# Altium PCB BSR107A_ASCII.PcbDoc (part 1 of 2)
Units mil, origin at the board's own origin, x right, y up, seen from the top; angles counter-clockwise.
Board outline 2500 x 2500 mil, 4 copper layers (Top Layer, Signal Layer 1, Signal Layer 2, Bottom Layer), stack 64.4 mil thick; 58 components, 15 nets, 89 pads, 265 vias.
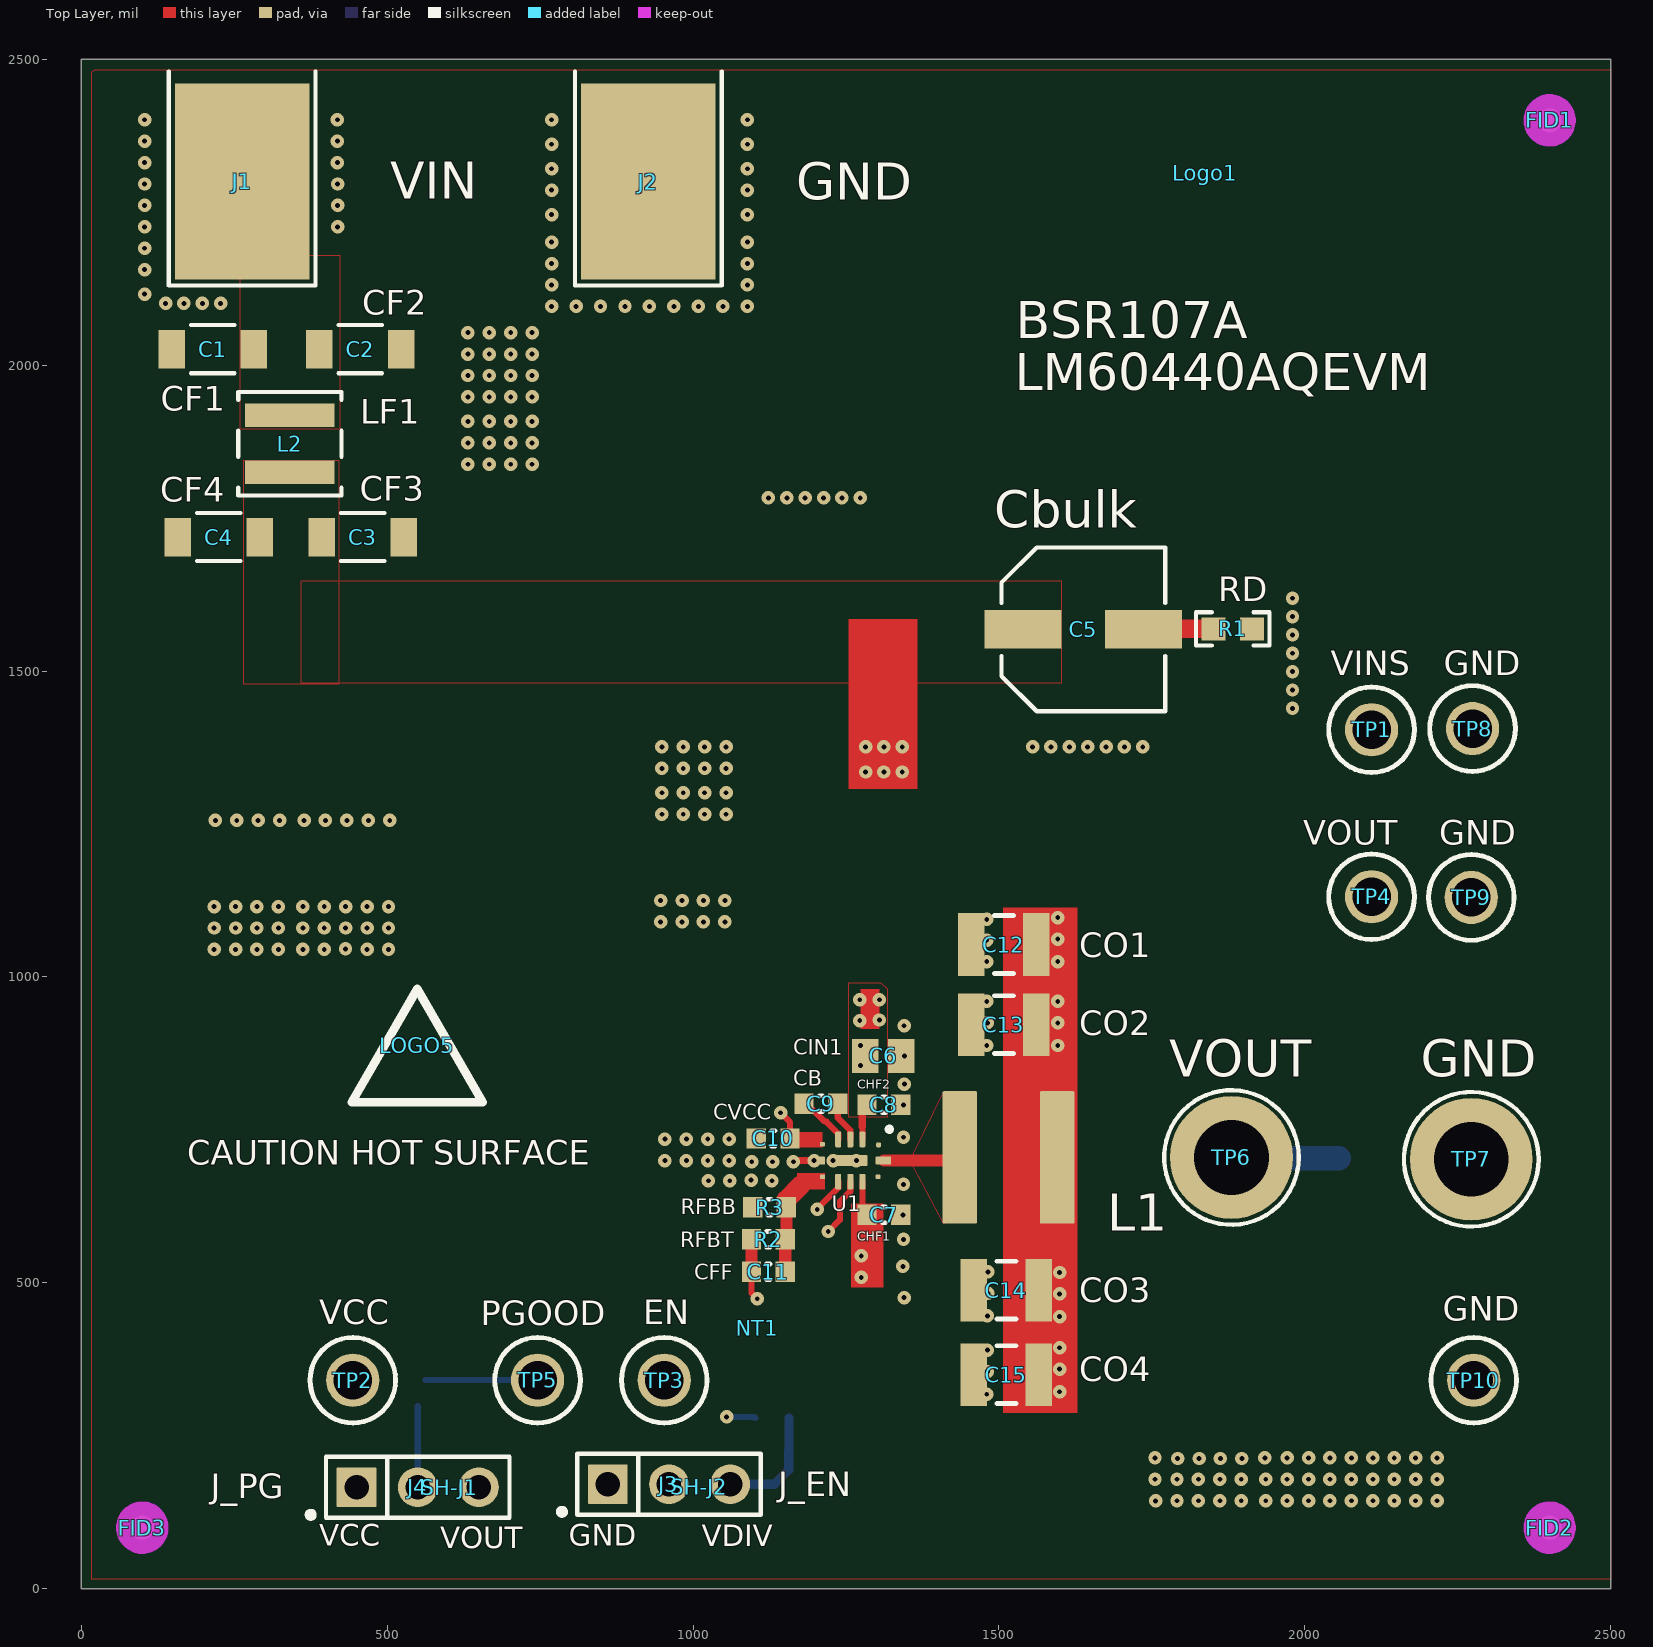
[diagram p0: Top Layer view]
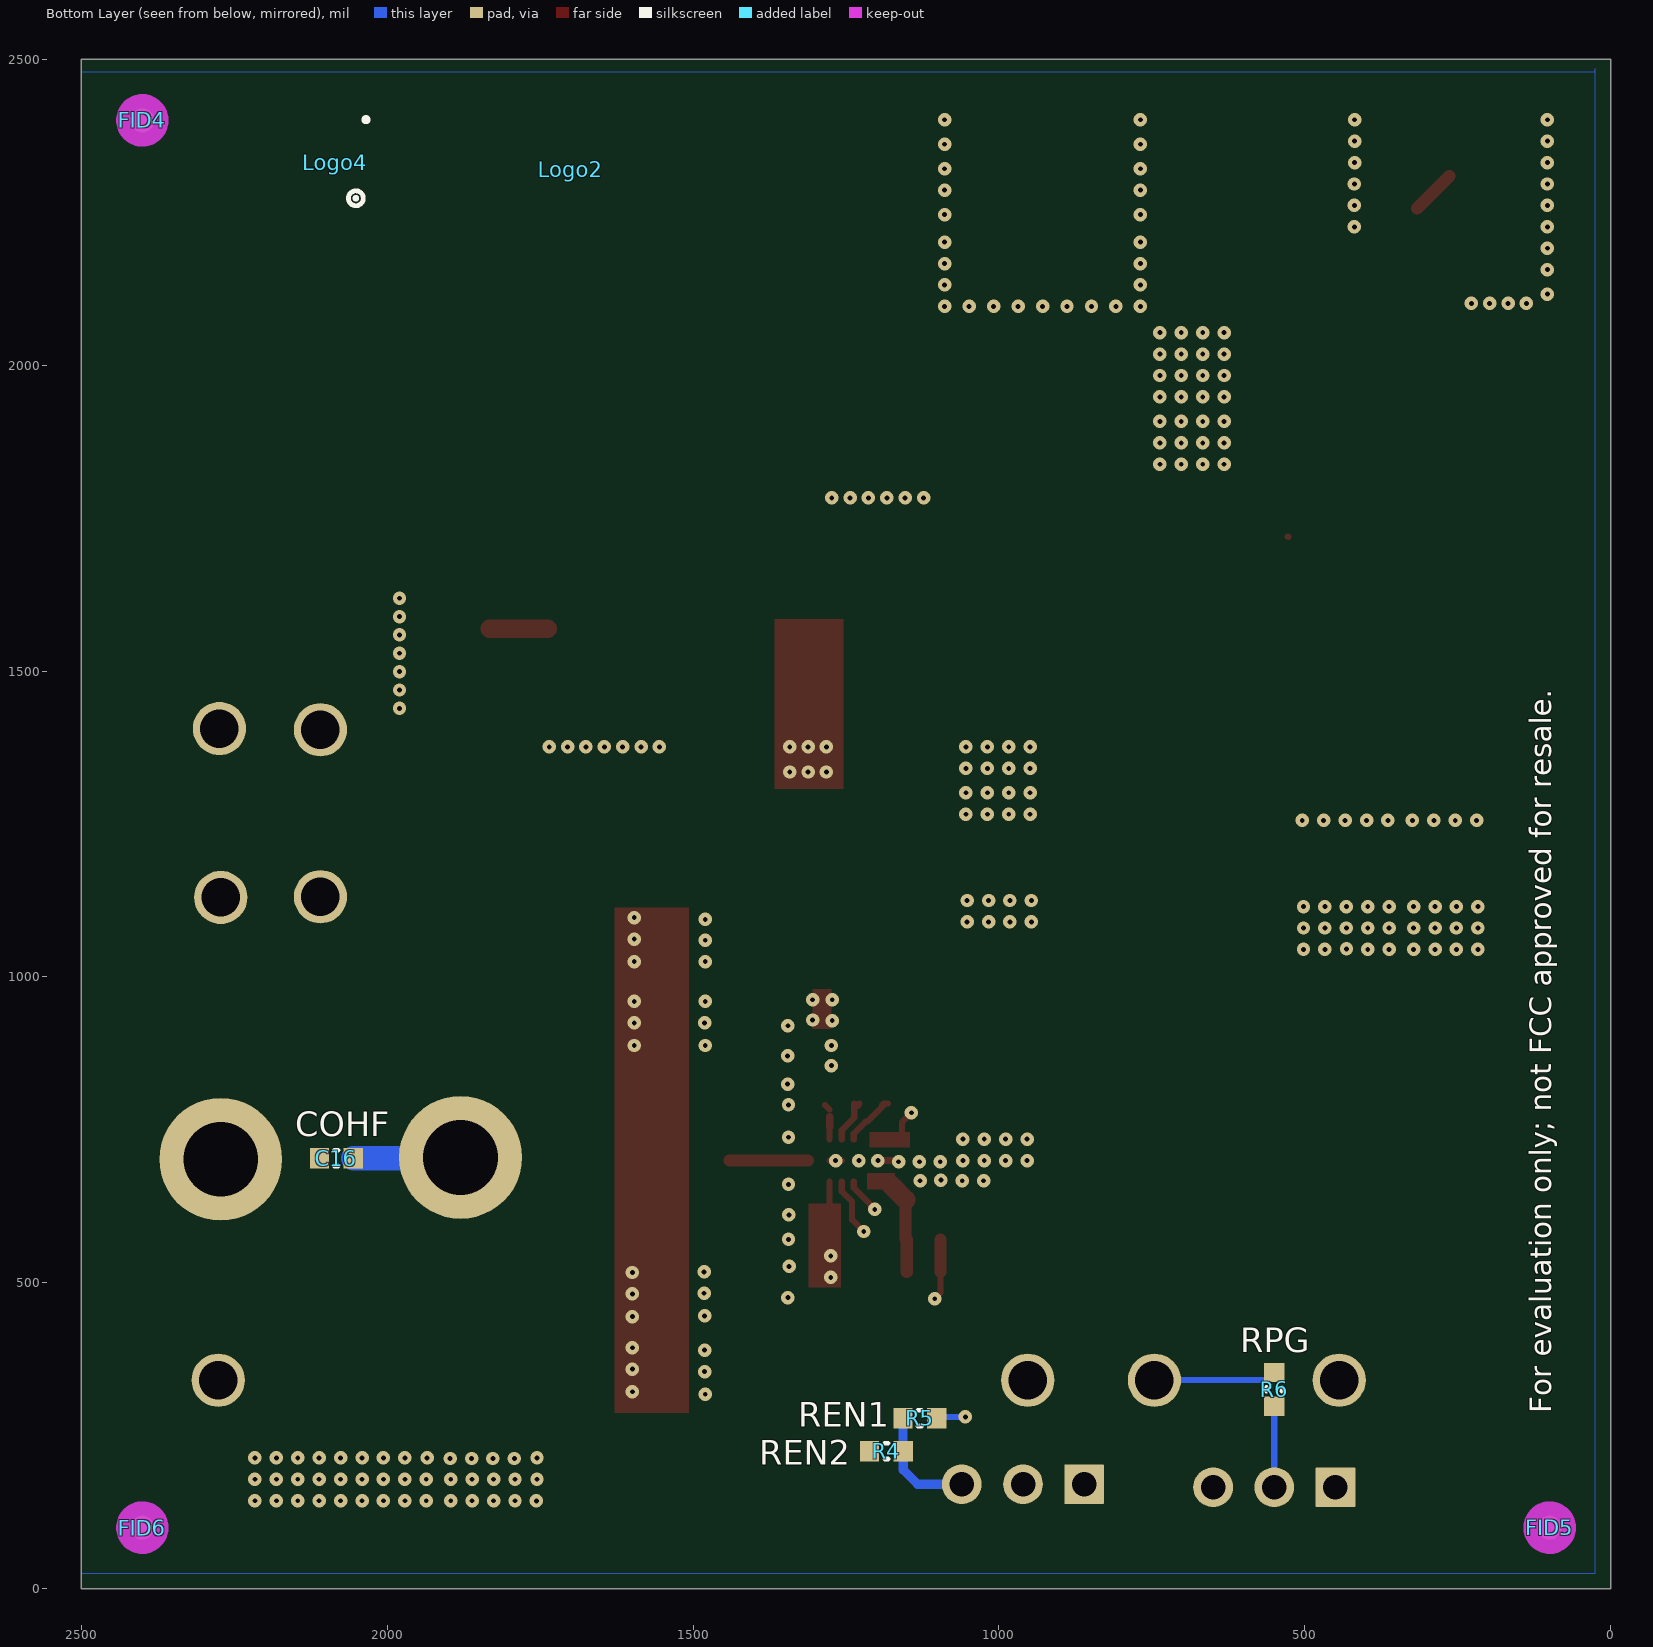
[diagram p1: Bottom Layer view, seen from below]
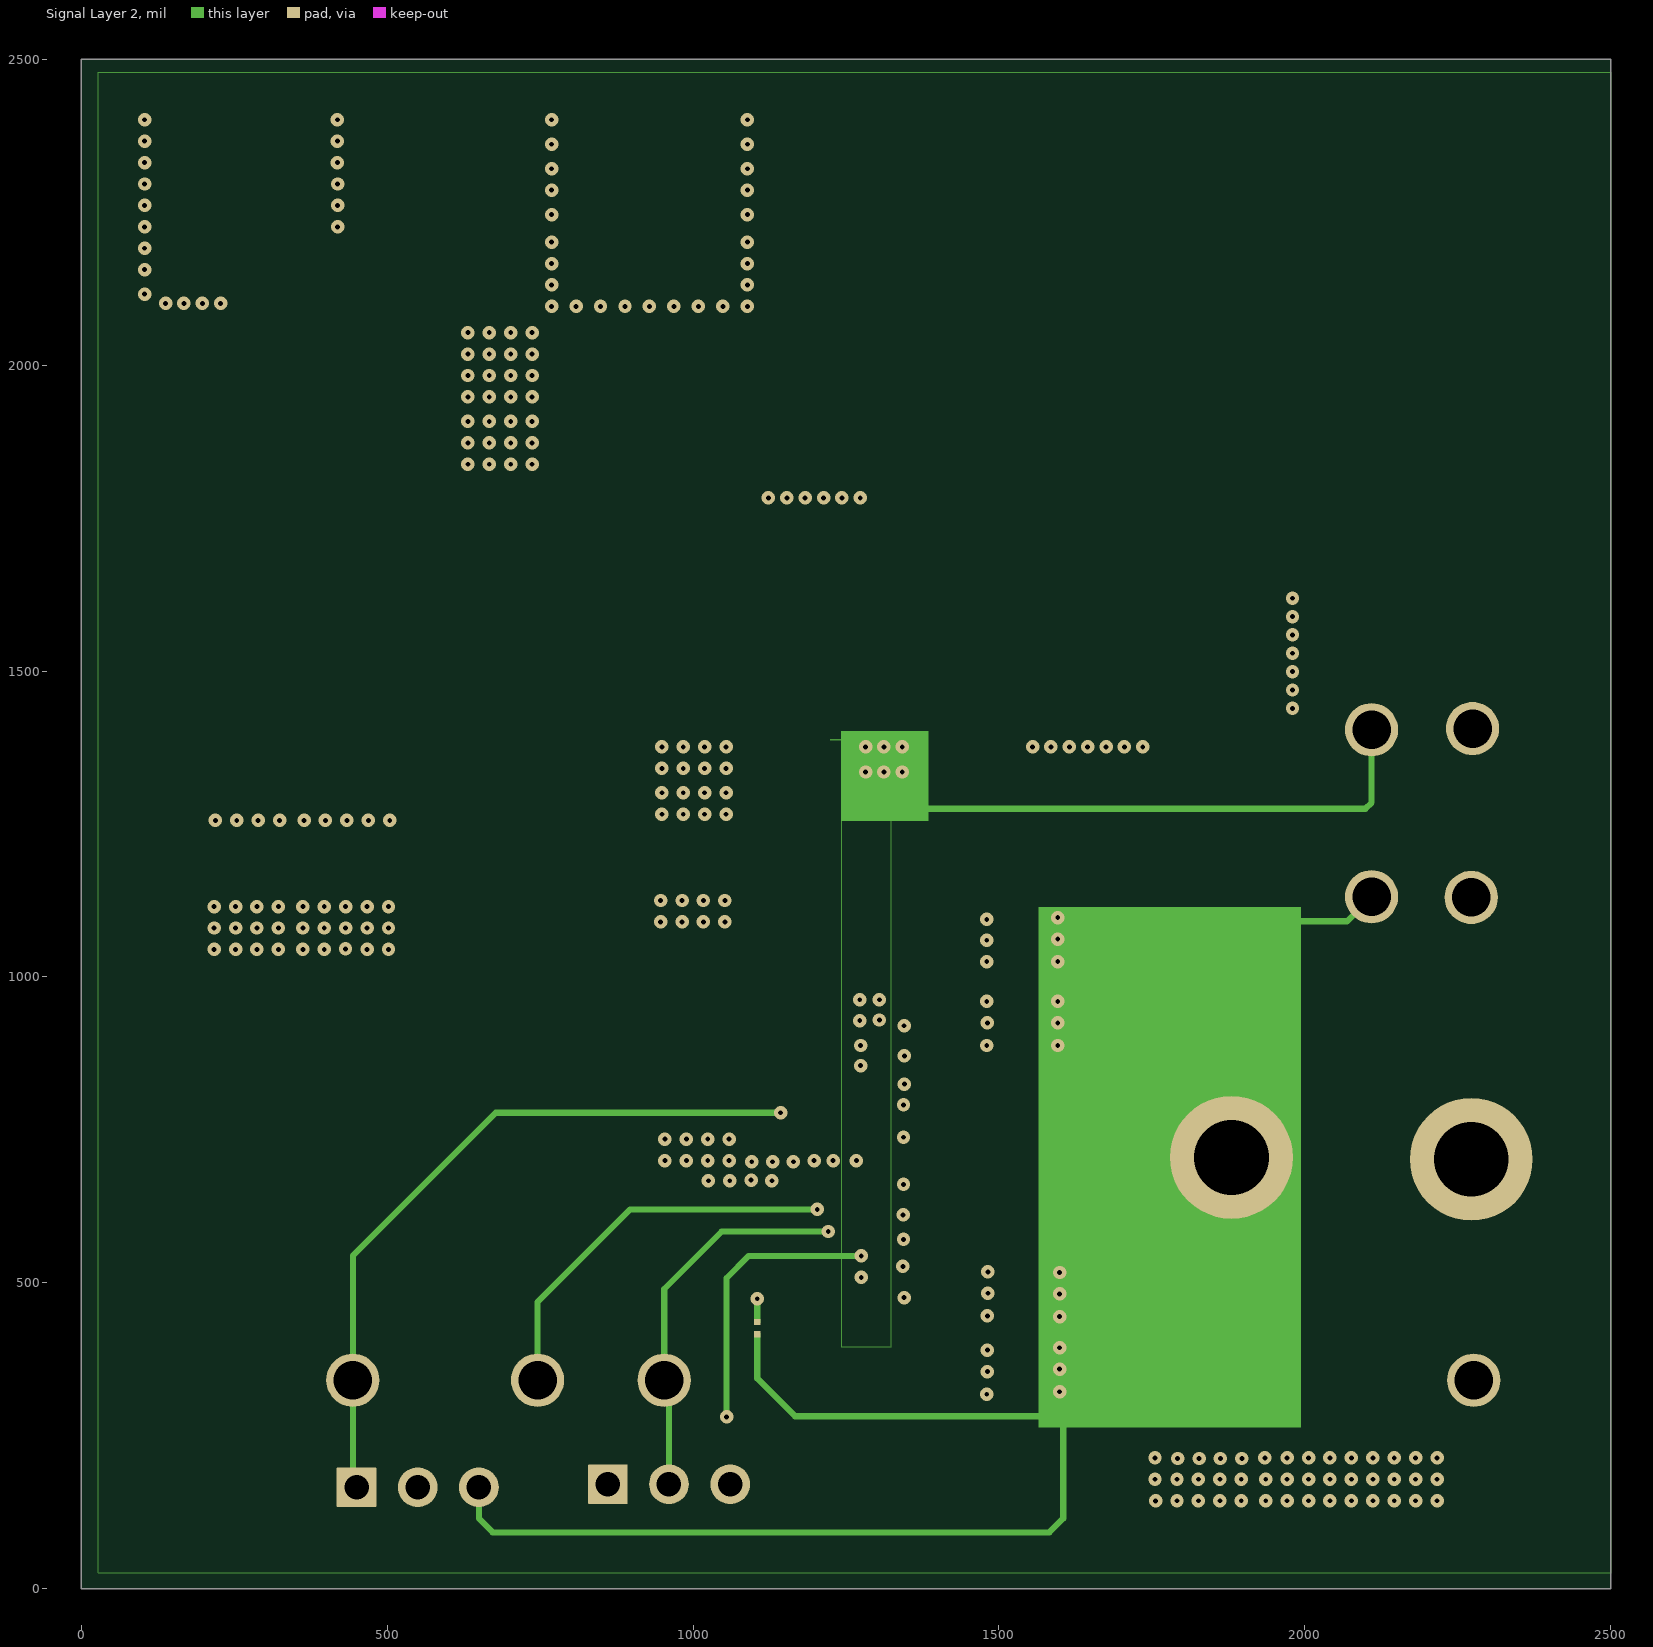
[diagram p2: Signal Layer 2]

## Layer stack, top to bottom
Top Solder: solder mask 0.4, Solder Resist, Dk 3.5
Top Layer: signal copper 2.8
Dielectric 3: core 14, FR-4 High TG, Dk 4.2
Signal Layer 1: signal copper 1.4
Dielectric 2: core 28, FR-4 High TG, Dk 4.2
Signal Layer 2: signal copper 1.4
Dielectric1: core 14, FR-4 HIgh TG, Dk 4.2
Bottom Layer: signal copper 2.8
Bottom Solder: solder mask 0.4, Solder Resist, Dk 3.5

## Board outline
0,0 0,2500 2500,2500 2500,0

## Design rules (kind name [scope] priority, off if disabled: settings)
AcuteAngle [All] p0: scope1count=1 scope1_0_kind=Board scope1_0_value=Board scope2count=1 scope2_0_kind=Board scope2_0_value=Board commentlength=0 minimum=4.50000000000000E+0001
AcuteAngle [All] p1: minimum=4.50000000000000E+0001 checktracksonly=FALSE
AssemblyTestPointUsage [All] p0: scope1count=1 scope1_0_kind=Board scope1_0_value=Board scope2count=1 scope2_0_kind=Board scope2_0_value=Board commentlength=0
AssemblyTestPointUsage [All] p1: valid=2
AssemblyTestpoint [All] p0: scope1count=1 scope1_0_kind=Board scope1_0_value=Board scope2count=1 scope2_0_kind=Board scope2_0_value=Board commentlength=0
BoardOutlineClearance [All] p0 off: scope1count=1 scope1_0_kind=Board scope1_0_value=Board scope2count=1 scope2_0_kind=Board scope2_0_value=Board commentlength=172 gap=40 // Protel DXP Scope 1 Expression Was: OnCopper and Not InComponentClass('Logo') and not InComponentClass('FiducialMark') and not InRegion(1000,500,4000,800) and not InPoly
BoardOutlineClearance BoardOutlineClearance_Poly [All] p0 off: scope1count=1 scope1_0_kind=Board scope1_0_value=Board scope2count=1 scope2_0_kind=Board scope2_0_value=Board commentlength=58 gap=25 // Protel DXP Scope 1 Expression Was: OnCopper and IsPoly
BoardOutlineClearance BoardOutlineClearance_MountingHoles [All] p0 off: scope1count=1 scope1_0_kind=Board scope1_0_value=Board scope2count=1 scope2_0_kind=Board scope2_0_value=Board commentlength=86 gap=40 // Protel DXP Scope 1 Expression Was: OnCopper and InComponentClass('Mounting Holes')
BoardOutlineClearance BoardOutlineClearance_MountingHoles [OnCopper and InComponentClass('Mounting Holes')] p1: gap=40 ignorepadtopadclearanceinfootprint=FALSE
BoardOutlineClearance BoardOutlineClearance_Poly [OnCopper and IsPoly] p2: gap=25 ignorepadtopadclearanceinfootprint=FALSE
BoardOutlineClearance [OnCopper and Not InComponentClass('Logo') and not InComponentClass('FiducialMark') and not InRegion(1000,500,4000,800) and not InPoly] p3: gap=40 ignorepadtopadclearanceinfootprint=FALSE
Clearance [All] p0: scope1count=1 scope1_0_kind=Board scope1_0_value=Board scope2count=1 scope2_0_kind=Board scope2_0_value=Board commentlength=0 gap=7.79
Clearance Clearance_FiducialMark [All] p0 off: scope1count=1 scope1_0_kind=Board scope1_0_value=Board scope2count=1 scope2_0_kind=Board scope2_0_value=Board commentlength=81 gap=0 // Protel DXP Scope 2 Expression Was: IsPad and InComponentClass('FiducialMark')
Clearance Clearance_Poly [All] p0 off: scope1count=1 scope1_0_kind=Board scope1_0_value=Board scope2count=1 scope2_0_kind=Board scope2_0_value=Board commentlength=48 gap=10 // Protel DXP Scope 1 Expression Was: InPolygon
Clearance Clearance_Keepouts [All] p0 off: scope1count=1 scope1_0_kind=Board scope1_0_value=Board scope2count=1 scope2_0_kind=Board scope2_0_value=Board commentlength=99 gap=0 // Protel DXP Scope 2 Expression Was: ((IsTrack Or IsArc) And Not InPoly) And IsFree and IsKeepOut
Clearance Clearance_Keepouts [((IsTrack Or IsArc) And Not InPoly) And IsFree and IsKeepOut vs ((IsTrack Or IsArc) And Not InPoly) And IsFree and IsKeepOut] p1: gap=0 ignorepadtopadclearanceinfootprint=FALSE
Clearance Clearance_Poly [InPolygon] p2: gap=10 ignorepadtopadclearanceinfootprint=FALSE except(0: Arc-Hole Track-Hole SMDPad-Hole THPad-Hole Via-Hole Fill-Hole Poly-Hole Region-Hole Text-Hole)
Clearance Clearance_FiducialMark [IsKeepOut and InComponentClass('FiducialMark') vs IsPad and InComponentClass('FiducialMark')] p3: gap=0 ignorepadtopadclearanceinfootprint=FALSE
Clearance [All] p4: gap=7.79 ignorepadtopadclearanceinfootprint=FALSE
ComponentClearance [All] p0: scope1count=1 scope1_0_kind=Board scope1_0_value=Board scope2count=1 scope2_0_kind=Board scope2_0_value=Board commentlength=0 gap=30 collisioncheckmode=3
ComponentClearance ComponentClearance_THtoTH [All] p0 off: scope1count=1 scope1_0_kind=Board scope1_0_value=Board scope2count=1 scope2_0_kind=Board scope2_0_value=Board commentlength=54 gap=30 collisioncheckmode=3 // Protel DXP Scope 2 Expression Was: IsThruComponent
ComponentClearance ComponentClearance_THtoSMT [All] p0 off: scope1count=1 scope1_0_kind=Board scope1_0_value=Board scope2count=1 scope2_0_kind=Board scope2_0_value=Board commentlength=53 gap=40 collisioncheckmode=3 // Protel DXP Scope 2 Expression Was: IsSMTComponent
ComponentClearance ComponentClearance_SmallPassives [All] p0 off: scope1count=1 scope1_0_kind=Board scope1_0_value=Board scope2count=1 scope2_0_kind=Board scope2_0_value=Board commentlength=508 gap=14.96 collisioncheckmode=3 // Protel DXP Scope 2 Expression Was: HasFootprint('0201*') or HasFootprint('0402*') or HasFootprint('0508') or HasFootprint('0603*') or HasFootprint('0612') or HasFootprint('0805*') or HasFootprint('0815*') or HasFootprint('0830*') or HasFootprint('1206*') or HasFootprint('1210*') or HasFootprint('1808*') or HasFootprint('1812*') or HasFootprint('1825*') or HasFootprint('2010*') or HasFootprint('2220*') or HasFootprint('2225*') or HasFootprint('2512*') or HasFootprint('2728*') or HasFootprint('3518*')
ComponentClearance ComponentClearance_MountingHoles [All] p0: scope1count=1 scope1_0_kind=ComponentClass scope1_0_value="Mounting Holes" scope2count=1 scope2_0_kind=Board scope2_0_value=Board commentlength=0 gap=250 collisioncheckmode=3
ComponentClearance ComponentClearance_ScrewToNut [All] p0 off: scope1count=1 scope1_0_kind=Board scope1_0_value=Board scope2count=1 scope2_0_kind=Board scope2_0_value=Board commentlength=71 gap=5 collisioncheckmode=3 // Protel DXP Scope 2 Expression Was: (HasFootprint('Keystone_1902C'))
ComponentClearance ComponentClearance_Logo [All] p0: scope1count=1 scope1_0_kind=ComponentClass scope1_0_value=Logo scope2count=1 scope2_0_kind=Board scope2_0_value=Board commentlength=0 gap=50 collisioncheckmode=3
ComponentClearance ComponentClearance_Shunt [All] p0: scope1count=1 scope1_0_kind=ComponentClass scope1_0_value=Header scope2count=1 scope2_0_kind=ComponentClass scope2_0_value=Shunt commentlength=0 gap=0 collisioncheckmode=3
ComponentClearance ComponentClearance_MountingHoles_FiducialMarks [All] p0: scope1count=1 scope1_0_kind=ComponentClass scope1_0_value="Mounting Holes" scope2count=1 scope2_0_kind=ComponentClass scope2_0_value=FiducialMark commentlength=0 gap=50 collisioncheckmode=3
ComponentClearance ComponentClearance_MountingHoles_FiducialMarks [InComponentClass('Mounting Holes') vs InComponentClass('FiducialMark')] p1: gap=50 collisioncheckmode=3 verticalgap=10 showdistances=FALSE
ComponentClearance ComponentClearance_Shunt [InComponentClass('Header') vs InComponentClass('Shunt')] p2: gap=0 collisioncheckmode=3 verticalgap=0 showdistances=FALSE
ComponentClearance ComponentClearance_Logo [InComponentClass('Logo')] p3: gap=50 collisioncheckmode=3 verticalgap=10 showdistances=FALSE
ComponentClearance ComponentClearance_ScrewToNut [(HasFootprint('NY PMS 440 0025 PH')) vs (HasFootprint('Keystone_1902C'))] p4: gap=5 collisioncheckmode=3 verticalgap=10 showdistances=FALSE
ComponentClearance ComponentClearance_MountingHoles [InComponentClass('Mounting Holes')] p5: gap=250 collisioncheckmode=3 verticalgap=100000 showdistances=FALSE
ComponentClearance ComponentClearance_SmallPassives [HasFootprint('0201*') or HasFootprint('0402*') or HasFootprint('0508') or HasFootprint('0603*') or HasFootprint('0612') or HasFootprint('0805*') or HasFootprint('0815*') or HasFootprint('0830*') or HasFootprint('1206*') or HasFootprint('1210*') or HasFootprint('1808*') or HasFootprint('1812*') or HasFootprint('1825*') or HasFootprint('2010*') or HasFootprint('2220*') or HasFootprint('2225*') or HasFootprint('2512*') or HasFootprint('2728*') or HasFootprint('3518*') vs HasFootprint('0201*') or HasFootprint('0402*') or HasFootprint('0508') or HasFootprint('0603*') or HasFootprint('0612') or HasFootprint('0805*') or HasFootprint('0815*') or HasFootprint('0830*') or HasFootprint('1206*') or HasFootprint('1210*') or HasFootprint('1808*') or HasFootprint('1812*') or HasFootprint('1825*') or HasFootprint('2010*') or HasFootprint('2220*') or HasFootprint('2225*') or HasFootprint('2512*') or HasFootprint('2728*') or HasFootprint('3518*')] p6: gap=14.96 collisioncheckmode=3 verticalgap=10 showdistances=FALSE
ComponentClearance ComponentClearance_THtoSMT [IsThruComponent vs IsSMTComponent] p7: gap=40 collisioncheckmode=3 verticalgap=30 showdistances=FALSE
ComponentClearance ComponentClearance_THtoTH [IsThruComponent vs IsThruComponent] p8: gap=30 collisioncheckmode=3 verticalgap=30 showdistances=FALSE
ComponentClearance [All] p9: gap=30 collisioncheckmode=3 verticalgap=10 showdistances=FALSE
DiffPairsRouting [All] p0: scope1count=1 scope1_0_kind=Board scope1_0_value=Board scope2count=1 scope2_0_kind=Board scope2_0_value=Board commentlength=0
DiffPairsRouting [All] p1: maxlimit=100 minlimit=10 mostfreqgap=10 toplayer_minwidth=15 toplayer_maxwidth=15 toplayer_prefwidth=15 midlayer1_minwidth=15 midlayer1_maxwidth=15 midlayer1_prefwidth=15 midlayer2_minwidth=15 midlayer2_maxwidth=15 midlayer2_prefwidth=15 bottomlayer_minwidth=15 bottomlayer_maxwidth=15 bottomlayer_prefwidth=15 maxuncoupledlength=1000
FabricationTestPointUsage TestPointUsage [All] p0: scope1count=1 scope1_0_kind=Board scope1_0_value=Board scope2count=1 scope2_0_kind=Board scope2_0_value=Board commentlength=0 valid=2 allowmultiple=FALSE
FabricationTestPointUsage TestPointUsage [All] p1: valid=2 allowmultiple=FALSE
FabricationTestpoint Testpoint [All] p0: scope1count=1 scope1_0_kind=Board scope1_0_value=Board scope2count=1 scope2_0_kind=Board scope2_0_value=Board commentlength=0 side=3 testpointundercomponent=TRUE minsize=40 maxsize=100 preferedsize=60 minholesize=0 maxholesize=40 preferedholesize=32 testpointgrid=1
FabricationTestpoint Testpoint [All] p1: side=3 testpointundercomponent=TRUE minsize=40 maxsize=100 preferedsize=60 minholesize=0 maxholesize=40 preferedholesize=32 testpointgrid=1 allowsidetop=TRUE allowsidebottom=TRUE usegrid=TRUE gridtolerance=0.01
FanoutControl Fanout_Small [All] p0 off: scope1count=1 scope1_0_kind=Board scope1_0_value=Board scope2count=1 scope2_0_kind=Board scope2_0_value=Board commentlength=84 // Protel DXP Scope 1 Expression Was: (CompPinCount < 5)   Fanout_Small (Default Rule)
FanoutControl Fanout_Default [All] p0: scope1count=1 scope1_0_kind=Board scope1_0_value=Board scope2count=1 scope2_0_kind=Board scope2_0_value=Board commentlength=30 // Fanout_Default (Default Rule)
FanoutControl Fanout_SOIC [All] p0 off: scope1count=1 scope1_0_kind=Board scope1_0_value=Board scope2count=1 scope2_0_kind=Board scope2_0_value=Board commentlength=71 // Protel DXP Scope 1 Expression Was: IsSOIC   Fanout_SOIC (Default Rule)
FanoutControl Fanout_BGA [All] p0 off: scope1count=1 scope1_0_kind=Board scope1_0_value=Board scope2count=1 scope2_0_kind=Board scope2_0_value=Board commentlength=69 // Protel DXP Scope 1 Expression Was: IsBGA   Fanout_BGA (Default Rule)
FanoutControl Fanout_LCC [All] p0 off: scope1count=1 scope1_0_kind=Board scope1_0_value=Board scope2count=1 scope2_0_kind=Board scope2_0_value=Board commentlength=69 // Protel DXP Scope 1 Expression Was: IsLCC   Fanout_LCC (Default Rule)
FanoutControl Fanout_LCC [IsLCC] p1: bgadir=Out bgaviamode=Centered fanoutstyle=Auto fanoutdirection=Alternating viagrid=1 // Fanout_LCC (Default Rule)
FanoutControl Fanout_BGA [IsBGA] p2: bgadir=Out bgaviamode=Centered fanoutstyle=Auto fanoutdirection=Alternating viagrid=1 // Fanout_BGA (Default Rule)
FanoutControl Fanout_Default [All] p4: bgadir=Out bgaviamode=Centered fanoutstyle=Auto fanoutdirection=Alternating viagrid=1 // Fanout_Default (Default Rule)
FanoutControl Fanout_Small [(CompPinCount < 5)] p5: bgadir=Out bgaviamode=Centered fanoutstyle=Auto fanoutdirection=OutThenIn viagrid=1 // Fanout_Small (Default Rule)
Height [All] p0: scope1count=1 scope1_0_kind=Board scope1_0_value=Board scope2count=1 scope2_0_kind=Board scope2_0_value=Board commentlength=0
HoleSize [All] p0: scope1count=1 scope1_0_kind=Board scope1_0_value=Board scope2count=1 scope2_0_kind=Board scope2_0_value=Board commentlength=0 absolutevalues=TRUE maxlimit=251 minlimit=7.87 maxpercent=80.000 minpercent=20.000
HoleSize [All] p1: absolutevalues=TRUE maxlimit=251 minlimit=7.87 maxpercent=80.000 minpercent=20.000
HoleToHoleClearance [All] p0: scope1count=1 scope1_0_kind=Board scope1_0_value=Board scope2count=1 scope2_0_kind=Board scope2_0_value=Board commentlength=0
LayerPairs [All] p0: scope1count=1 scope1_0_kind=Board scope1_0_value=Board scope2count=1 scope2_0_kind=Board scope2_0_value=Board commentlength=0 enforce=TRUE
MinimumAnnularRing [All] p0: scope1count=1 scope1_0_kind=Board scope1_0_value=Board scope2count=1 scope2_0_kind=Board scope2_0_value=Board commentlength=0 minimumring=5
MinimumAnnularRing MinimumAnnularRing_ThermalPadVias [All] p0 off: scope1count=1 scope1_0_kind=Board scope1_0_value=Board scope2count=1 scope2_0_kind=Board scope2_0_value=Board commentlength=63 minimumring=5.91 // Protel DXP Scope 1 Expression Was: IsVia and InAnyComponent
MinimumAnnularRing MinimumAnnularRing_ThermalPadVias [IsVia and InAnyComponent] p1: minimumring=5.91
MinimumAnnularRing [All] p2: minimumring=5
MinimumSolderMaskSliver [All] p0: scope1count=1 scope1_0_kind=Board scope1_0_value=Board scope2count=1 scope2_0_kind=Board scope2_0_value=Board commentlength=0
MinimumSolderMaskSliver MinimumSolderMaskSliver_Logo [All] p0: scope1count=1 scope1_0_kind=ComponentClass scope1_0_value=Logo scope2count=1 scope2_0_kind=ComponentClass scope2_0_value=Logo commentlength=0
MinimumSolderMaskSliver MinimumSolderMaskSliver_Logo [InComponentClass('Logo') vs InComponentClass('Logo')] p1: minsoldermaskwidth=0.7
MinimumSolderMaskSliver [All] p2: minsoldermaskwidth=3.94
NetAntennae [All] p0: scope1count=1 scope1_0_kind=Board scope1_0_value=Board scope2count=1 scope2_0_kind=Board scope2_0_value=Board commentlength=0
PasteMaskExpansion [All] p0: scope1count=1 scope1_0_kind=Board scope1_0_value=Board scope2count=1 scope2_0_kind=Board scope2_0_value=Board commentlength=0 expansion=0
PlaneClearance [All] p0: scope1count=1 scope1_0_kind=Board scope1_0_value=Board scope2count=1 scope2_0_kind=Board scope2_0_value=Board commentlength=0 clearance=20
PlaneConnect [All] p0: scope1count=1 scope1_0_kind=Board scope1_0_value=Board scope2count=1 scope2_0_kind=Board scope2_0_value=Board commentlength=0 planeconnectstyle=Relief reliefexpansion=10 reliefentries=4 reliefconductorwidth=10 reliefairgap=10
PlaneConnect [All] p1: planeconnectstyle=Relief reliefexpansion=10 reliefentries=4 reliefconductorwidth=10 reliefairgap=10
PolygonConnect [All] p0: scope1count=1 scope1_0_kind=Board scope1_0_value=Board scope2count=1 scope2_0_kind=Board scope2_0_value=Board commentlength=0 connectstyle=Direct reliefconductorwidth=10 reliefentries=4 polygonreliefangle="90 Angle"
PolygonConnect [All] p1: connectstyle=Direct reliefconductorwidth=10 reliefentries=4 polygonreliefangle="90 Angle" airgapwidth=10
RoutingCorners [All] p0: scope1count=1 scope1_0_kind=Board scope1_0_value=Board scope2count=1 scope2_0_kind=Board scope2_0_value=Board commentlength=0 cornerstyle=45-Degree minsetback=100 maxsetback=100
RoutingLayers [All] p0: scope1count=1 scope1_0_kind=Board scope1_0_value=Board scope2count=1 scope2_0_kind=Board scope2_0_value=Board commentlength=0 top layer=Automatic mid layer 1=Automatic mid layer 2=Automatic bottom layer=Automatic
RoutingPriority [All] p0: scope1count=1 scope1_0_kind=Board scope1_0_value=Board scope2count=1 scope2_0_kind=Board scope2_0_value=Board commentlength=0
RoutingTopology [All] p0: scope1count=1 scope1_0_kind=Board scope1_0_value=Board scope2count=1 scope2_0_kind=Board scope2_0_value=Board commentlength=0 topology=Shortest
RoutingVias [All] p0: scope1count=1 scope1_0_kind=Board scope1_0_value=Board scope2count=1 scope2_0_kind=Board scope2_0_value=Board commentlength=0 holewidth=16 width=34 viastyle="Through Hole" minholewidth=7.87 minwidth=18 maxholewidth=40 maxwidth=65
RoutingVias ThermalPadVias [All] p0 off: scope1count=1 scope1_0_kind=Board scope1_0_value=Board scope2count=1 scope2_0_kind=Board scope2_0_value=Board commentlength=63 holewidth=7.87 width=19.68 viastyle="Through Hole" minholewidth=7.87 minwidth=19.68 maxholewidth=12.99 maxwidth=23.62 // Protel DXP Scope 1 Expression Was: IsVia and InAnyComponent
RoutingVias ThermalPadVias [IsVia and InAnyComponent] p1: holewidth=7.87 width=19.68 viastyle="Through Hole" minholewidth=7.87 minwidth=19.68 maxholewidth=12.99 maxwidth=23.62
RoutingVias [All] p2: holewidth=16 width=34 viastyle="Through Hole" minholewidth=7.87 minwidth=18 maxholewidth=40 maxwidth=65
ShortCircuit [All] p0: scope1count=1 scope1_0_kind=Board scope1_0_value=Board scope2count=1 scope2_0_kind=Board scope2_0_value=Board commentlength=0 allowed=FALSE
SilkToBoardRegionClearance [All] p0 off: scope1count=1 scope1_0_kind=Board scope1_0_value=Board scope2count=1 scope2_0_kind=Board scope2_0_value=Board commentlength=130 // Protel DXP Scope 1 Expression Was: Not ((IsComment or IsDesignator) And (Hide <> 'False')) and not InRegion(1000,500,4000,800)
SilkToBoardRegionClearance [Not ((IsComment or IsDesignator) And (Hide <> 'False')) and not InRegion(1000,500,4000,800)] p1:
SilkToSilkClearance [All] p0: scope1count=1 scope1_0_kind=Board scope1_0_value=Board scope2count=1 scope2_0_kind=Board scope2_0_value=Board commentlength=0
SilkToSilkClearance SilkToSilkClearance_Pb-FreeLogo [All] p0 off: scope1count=1 scope1_0_kind=Board scope1_0_value=Board scope2count=1 scope2_0_kind=Board scope2_0_value=Board commentlength=120 // Protel DXP Scope 2 Expression Was: (HasFootprint('Pb-Free_Overlay_Medium') OR HasFootprint('Pb-Free_Overlay_Small'))
SilkToSilkClearance SilkToSilkClearance_Pb-FreeLogo [(HasFootprint('Pb-Free_Overlay_Medium') OR HasFootprint('Pb-Free_Overlay_Small')) vs (HasFootprint('Pb-Free_Overlay_Medium') OR HasFootprint('Pb-Free_Overlay_Small'))] p1: silktosilkclearance=0
SilkToSilkClearance [All] p2: silktosilkclearance=4
SilkToSolderMaskClearance "Silk to Solder Mask Opening" [All] p0: scope1count=1 scope1_0_kind=Board scope1_0_value=Board scope2count=1 scope2_0_kind=Board scope2_0_value=Board commentlength=0
SilkToSolderMaskClearance SilkToComponentPadClearance [All] p0 off: scope1count=1 scope1_0_kind=Board scope1_0_value=Board scope2count=1 scope2_0_kind=Board scope2_0_value=Board commentlength=87 // Protel DXP Scope 1 Expression Was: (IsPad or IsFill or IsRegion) and InAnycomponent
SilkToSolderMaskClearance SilkToComponentPadClearance [(IsPad or IsFill or IsRegion) and InAnycomponent] p1: minsilkscreentomaskgap=5 clearancetoexposedcopper=TRUE
SilkToSolderMaskClearance "Silk to Solder Mask Opening" [All] p2: minsilkscreentomaskgap=4 clearancetoexposedcopper=FALSE
SolderMaskExpansion [All] p0: scope1count=1 scope1_0_kind=Board scope1_0_value=Board scope2count=1 scope2_0_kind=Board scope2_0_value=Board commentlength=0 expansion=1.97
SolderMaskExpansion [All] p1: expansion=1.97
UnRoutedNet [All] p0: scope1count=1 scope1_0_kind=Board scope1_0_value=Board scope2count=1 scope2_0_kind=Board scope2_0_value=Board commentlength=0
UnpouredPolygon [All] p0: scope1count=1 scope1_0_kind=Board scope1_0_value=Board scope2count=1 scope2_0_kind=Board scope2_0_value=Board commentlength=0
Width [All] p0: scope1count=1 scope1_0_kind=Board scope1_0_value=Board scope2count=1 scope2_0_kind=Board scope2_0_value=Board commentlength=0 maxlimit=100 minlimit=6 preferedwidth=10
Width [All] p1: maxlimit=100 minlimit=6 preferedwidth=10 checkconnectedcopper=TRUE
15 further rules are at their usual default settings.

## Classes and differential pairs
component class FiducialMark: FID1 FID2 FID3 FID4 FID5 FID6
component class Shunt: SH-J1 SH-J2
component class Header: J3 J4
component class BSR107A_EVM: 3 C1 C2 C3 C4 C5 C6 C7 C8 C9 C10 C11 C12 C13 C14 C15 C16 CB CHF2 CIN1 COUT1 GND GND4 GND5 J1 J2 J3 J4 L1 L2 NT1 R1 R2 R3 R4 R5 R6 TP1 TP2 TP3 TP4 TP5 TP6 TP7 TP8 TP9 TP10 U1 vin
component class AssemblyNote: ZZ2 ZZ3 ZZ4 ZZ5 ZZ6
component class BSR107A_EVM_Hardware: FID1 FID2 FID3 FID4 FID5 FID6 Logo1 Logo2 Logo3 Logo4 LOGO5 SH-J1 SH-J2 ZZ2 ZZ3 ZZ4 ZZ5 ZZ6
component class Logo: Logo1

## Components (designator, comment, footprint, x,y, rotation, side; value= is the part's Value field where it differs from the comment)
C1 "CF1" 1206_180 215,2026 r180 top
C2 "CF2" 1206_180 456,2026 r0 top
C3 "CF3" 1206_180 460,1719 r0 top
C4 "CF4" 1206_180 225,1719 r180 top
C5 "Cbulk" SM_RADIAL_D 1638,1568 r0 top
C6 "CIN1" 0805L 1311,871 r0 top
C7 "CHF1" 0603L 1312,611 r0 top
C8 "CHF2" 0603L 1312,791 r0 top
C9 "CB" 0603L 1209,793 r180 top
C10 "CVCC" 0603L 1131,736 r180 top
C11 "CFF" 0603L 1123,518 r0 top
C12 "CO1" 1210L 1508,1053 r180 top
C13 "CO2" 1210_270L 1508,922 r180 top
C14 "CO3" 1210_270L 1512,488 r180 top
C15 "CO4" 1210L 1512,350 r180 top
C16 "COHF" 0603L 2083,704 r0 bottom
FID1 "Fiducial" Fiducial10-20 2400,2400 r0 top
FID2 "Fiducial" Fiducial10-20 2400,100 r0 top
FID3 "Fiducial" Fiducial10-20 100,100 r0 top
FID4 "Fiducial" Fiducial10-20 2400,2400 r180 bottom
FID5 "Fiducial" Fiducial10-20 100,100 r180 bottom
FID6 "Fiducial" Fiducial10-20 2400,100 r180 bottom
J1 "VIN" 6091 263,2485 r270 top
J2 "GND" 6092 927,2485 r270 top
J3 "J_EN" Samtec_HTSW-103-07-G-S 960.67,170.89 r0 top
J4 "J_PG" Samtec_HTSW-103-07-G-S 550,166 r0 top
L1 "XAL6060-682MEB" XAL6060 1515.5,705 r0 top
L2 "LF1" XAL4030 341,1871.5 r270 top
Logo1 "Texas Instruments" TI_Stacked_Overlay_Small 1836.89,2313.76 r0 top
Logo2 "CE Mark" CE_Mark_5mm 1699.85,2319.94 r180 bottom
Logo3 "FCC disclaimer" FCC_disclaimer -478.56,846.5 r180 bottom
Logo4 "WEEE logo" WEEE_Minimum 2085.16,2331 r180 bottom
LOGO5 "CAUTION HOT SURFACE" IEC_HotSurface_Small 549,888 r0 top
NT1 "Net-Tie" Net-Tie_10mil 1105,426 r270 top net-tie
R1 "RD" 0603 1882,1569 r180 top
R2 "RFBT" 0603L 1123,571 r180 top
R3 "RFBB" 0603L 1125,624 r0 top
R4 "REN2" 0603L 1184,225 r180 bottom
R5 "REN1" 0603L 1129.35,279 r180 bottom
R6 "RPG" 0603L 550,326 r90 bottom
SH-J1 "SNT-100-BK-G" SNT-100-BK-G 602,166 r180 top
SH-J2 "SNT-100-BK-G" SNT-100-BK-G 1010,167 r180 top
TP1 "VINS" Keystone5010 2109,1404 r0 top
TP2 "VCC" Keystone5014 444,341 r0 top
TP3 "EN" Keystone5014 953,341 r0 top
TP4 "VOUT" Keystone5010 2109,1131 r0 top
TP5 "PGOOD" Keystone5014 746,341 r0 top
TP6 "VOUT" Keystone1503-2 1880,705 r0 top
TP7 "GND" Keystone1503-2 2272,702 r0 top
TP8 "GND" Keystone5011 2274,1406 r0 top
TP9 "GND" Keystone5011 2272,1130 r0 top
TP10 "GND" Keystone5011 2276,341 r0 top
U1 "LM60440-Q1" RPK0013A 1257,700 r270 top
ZZ2 "These assemblies are ESD sensitive, ESD precautions shall be observed." AssemblyNote 52.27,3634.11 r0 top
ZZ3 "These assemblies must be clean and free from flux and all contaminants. Use of no clean flux is not acceptable." AssemblyNote 52.27,3545.56 r0 top
ZZ4 "These assemblies must comply with workmanship standards IPC-A-610 Class 2, unless otherwise specified." AssemblyNote 52.27,3457 r0 top
ZZ5 "Place shunt jumper (SH-J1) on jumper (J3) in position 2-3" AssemblyNote 50,3269.73 r0 top
ZZ6 "Place shunt jumper (SH-J2) on jumper (J4) in position 2-3" AssemblyNote 51,3362.73 r0 top

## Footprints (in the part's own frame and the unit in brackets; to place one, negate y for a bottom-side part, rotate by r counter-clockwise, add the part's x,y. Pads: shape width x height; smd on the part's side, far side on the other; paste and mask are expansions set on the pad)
0603 [mm] "0603 from SM-752 data"
  rect 1x0.95 smd: 1(-0.8,0) 2(0.8,0)
  silkscreen extent -1.52,-0.69 1.52,0.69
0603L [mm] "0603 from SM-752 data"
  rect 0.8x0.85 smd: 1(-0.7,0) 2(0.7,0)
  silkscreen extent -0.07,-0.33 0.07,0.33
0805L [mm] "0805 from SM-752 data"
  rect 1.1x1.4 smd: 1(-0.75,0) 2(0.75,0)
1206_180 [mm] "1206_180"
  rect 1.1x1.6 smd: 1(-1.7,0) 2(1.7,0)
  silkscreen extent -0.9,-1 0.9,1
1210_270L [mm] "1210"
  rect 1.1x2.6 smd: 1(-1.35,0) 2(1.35,0)
  silkscreen extent -0.4,-1.2 0.4,1.2
1210L [mm] "1210 from SM-752 data"
  rect 1.1x2.6 smd: 1(-1.35,0) 2(1.35,0)
  silkscreen extent -0.4,-1.2 0.4,1.2
6091 [mil] "Keystone Insulated End Launch Banana Jack"
  rect 320x220 smd: 1(185,0)
  silkscreen extent 5,-120 355,120
6092 [mil] "Keystone Insulated End Launch Banana Jack"
  rect 320x220 smd: 1(185,0)
  silkscreen extent 5,-120 355,120
AssemblyNote [mil] "Assembly Note"
CE_Mark_5mm [mil] "Minimum text height for CE Mark"
FCC_disclaimer [mil]
Fiducial10-20 [mm]
  round 1 smd mask+0: 1(0,0)
  Top Layer keep-out circle w1.178: c0,0 r0.5
IEC_HotSurface_Small [mil]
  silkscreen extent -107,-93 107,92
Keystone1503-2 [mm] "Double Turret"
  round 5.1 hole 3.1: 1(0,0)
  silkscreen extent -2.79,-2.79 2.79,2.79
Keystone5010 [mil] "Keystone Multipurpose loops"
  round 87 hole 63: 1(0,0)
  silkscreen extent -70,-70 70,70
Keystone5011 [mil] "Keystone Multipurpose loops"
  round 87 hole 63: 1(0,0)
  silkscreen extent -70,-70 70,70
Keystone5014 [mil] "Keystone Multipurpose loops"
  round 87 hole 63: 1(0,0)
  silkscreen extent -70,-70 70,70
Net-Tie_10mil [mil] "10mil net tie, no solder mask opening, no solder paste"
  rect 10x10 on Mid2 paste-5 mask+0: 1(-10,0) 2(10,0)
RPK0013A [mm] "QFN, 13-Leads, Body 2x3mm, Ptich 0.5mm"
  rrect50% 0.2x0.2 smd: 1(-0.65,1.175) 5(-0.675,-1.15) 7(0.675,-1.15) 11(0.675,1.15)
  rrect40% 0.65x0.25 smd: 2(-0.875,0.5) 3(-0.875,0) 4(-0.875,-0.5) 8(0.875,-0.5) 9(0.875,0) 10(0.875,0.5)
  rrect29% 0.35x0.65 smd: 6(0,-1.375) 12(0,1.375)
  rrect22% 0.45x1.45 smd: 13(0,0)
Samtec_HTSW-103-07-G-S [mm] "Samtec 100mil, 1x3, 230 mil above insulator"
  rrect6% 1.65x1.65 hole 1.016: 1(-2.54,0)
  round 1.65 hole 1.016: 2(0,0) 3(2.54,0)
  silkscreen extent -4.57,-1.27 3.81,1.27
SM_RADIAL_D [mm] "6.3 x 5.8mm:  Panasonic D"
  rect 3.2x1.6 smd: 1(-2.5,0) 2(2.5,0)
  silkscreen extent -3.4,-3.4 3.4,3.4
SNT-100-BK-G [mil] "Samtec STEP model"
  round 1 on Mech3: 0(0,0)
TI_Stacked_Overlay_Small [mil]
WEEE_Minimum [mil] "WEEElie bin"
  silkscreen extent 22,-71 54,74
XAL4030 [mil] "Coilcraft XAL4030 7/18/12"
  rect 38x146 smd: 1(-46.5,0) 2(46.5,0)
  silkscreen extent -85,-85 85,85
XAL6060 [mm] "Coilcraft recommended land pattern Document 887-4 Revised 01/14/18"
  rrect7% 1.43x5.5 smd: 1(-2.019,0) 2(2.019,0)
